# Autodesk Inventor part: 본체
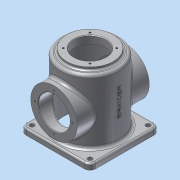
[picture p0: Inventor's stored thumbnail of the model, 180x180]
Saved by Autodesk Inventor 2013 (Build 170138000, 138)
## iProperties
Created: 2015-10
Part Number: 본체
Material: 알루미늄 6061
Document SubType Name: Modeling
Designer: ST4
Density: 2.71 g/cm^3
Mass: 989.141 g
Surface Area: 1040.66 cm^2
Volume: 364.997 cm^3
Author: ST4
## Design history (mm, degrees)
sketch "스케치1"
  geometry: L1 (-50, 60)-(50, 60); L2 (60, 50)-(60, -50); L3 (50, -60)-(-50, -60); L4 (-60, -50)-(-60, 50); A1 r 10 centre (-50, 50) between (-50, 60) and (-60, 50); A2 r 10 centre (50, 50) between (60, 50) and (50, 60); A3 r 10 centre (50, -50) between (50, -60) and (60, -50); A4 r 10 centre (-50, -50) between (-60, -50) and (-50, -60); 4 further points
  constraints: 8 end point, 8 point on circle, 8 tangent, 6 point on line, 4 centre point, 3 equal radius, 2 parallel, 1 horizontal, 1 perpendicular
  dimensions: "d0" = 120 distance of point (60, -60) point (-60, -60); "d2" = 120 distance of point (-60, -60) point (-60, 60); "d3" = 60 distance from line of point (0, 0) L3; "d4" = 60 distance from line of point (0, 0) L4; "d5" = 10 radius of A1
extrude "돌출1" new body sketch "스케치1" distance "d6" = 10; taper "d7" = 0 deg
sketch "스케치2"
  geometry: L1 (60, 10)-(60, 0) reference; L2 (60, 0)-(-60, 0) reference; L3 (-60, 0)-(-60, 10) reference; L4 (-60, 10)-(60, 10) reference; L5 (0, 0)-(0, 129.105); L6 (-28, 125)-(-40, 125); L7 (-40, 125)-(-40, 123); L8 (-43, 120)-(-45, 120); L9 (-50, 115)-(-50, 10); L10 (-27, 124)-(-27, 112); L11 (-27, 112)-(-42, 112); L12 (-45, 109)-(-45, 10); L13 (-28, 125)-(-27, 124); A1 r 5 centre (-45, 115) between (-45, 120) and (-50, 115); A2 r 3 centre (-43, 123) between (-43, 120) and (-40, 123); A3 r 3 centre (-42, 109) between (-42, 112) and (-45, 109); 2 further points
  constraints: 18 end point, 6 perpendicular, 6 point on circle, 6 point on line, 6 tangent, 3 centre point, 2 parallel
  dimensions: "d10" = 100 diameter of point (-50, 120) L5; "d11" = 80 diameter of L6.end L5; "d12" = 125 distance between parallel lines of L6 L2; "d14" = 110 distance between parallel lines of L8 L4; "d15" = 5 radius of A1; "d16" = 3 radius of A2; "d17" = 54 diameter of L10 L5; "d18" = 13 distance between parallel lines of L11 L6; "d19" = 90 diameter of L12 L5; "d20" = 1 distance of L6.start point (-27, 125); "d21" = 1 distance of L10.start point (-27, 125) (= d20); "d22" = 3 radius of A3
revolve "회전1" sketch "스케치2" stored, may be unused: angle "d23" = 90 deg
sketch "스케치3"
  geometry: C1 r 45 at (0, 0); 1 further point
  constraints: 1 centre point, 1 coincident
  dimensions: "d24" = 90 diameter of C1
extrude "돌출2" cut sketch "스케치3" distance "d26" = 10; taper "d27" = 0 deg
node "작업 평면1"
chamfer "모따기3" distance "d47" = 1; stored, may be unused: second distance "d48" = 2, angle "d49" = 45 deg
fillet "모깎기3" dims "d50" = 5
fillet "모깎기4" dims "d51" = 3
sketch "스케치6"
  geometry: C1 r 55 at (0, 0) reference; C2 r 4 at (50, -50); C3 r 4 at (50, 50); C4 r 4 at (-50, 50); C5 r 4 at (-50, -50); A1 r 7 centre (50, -50) between (50, -57) and (57, -50) reference
  constraints: 4 centre point, 1 coincident, 9 other
  dimensions: "d52" = 8 diameter of C2; "d56" = 360 deg dimension on C1.centre C2.centre (derived)
extrude "돌출5" cut sketch "스케치6" distance "d58" = 10; taper "d59" = 0 deg
sketch "스케치7" dims "d61" = 65
  geometry: L1 (0, 0)-(0, 28); L2 (0, 0)-(-28.284, 28.284); 3 further points
  constraints: 4 end point, 1 coincident, 1 point on line, 1 vertical, 1 vertical alignment, 6 other
  dimensions: "d60" = 45 deg angle of L1 L2
hole "구멍1" sketch "스케치7" at (-22.981, 22.981) diameter "d63" = 3.242; stored, may be unused: countersink angle "d67" = 90 deg, drill point angle "d69" = 118 deg; dims "d64" = 8, "d65" = 4, "d66" = 2, "d68" = 10
node "작업 평면3"
  node "작업 평면2"
sketch "스케치10"
  geometry: L1 (-5.17, -18.655)-(-5.17, 33.655); L2 (-5.17, 33.655)-(5.17, 33.655); L3 (5.17, 33.655)-(5.17, -18.655); L4 (5.17, -18.655)-(-5.17, -18.655); L5 (0, 33.655)-(0, -18.655); L6 (5.17, 7.5)-(-5.17, 7.5); L7 (-46, -62.5)-(46, -62.5) reference; 1 further point
  constraints: 4 end point, 4 midpoint, 2 other
  dimensions: "d98" = 0 distance from line of point (0, -62.5) L5; "d99" = 70 distance from line of L6.end L7
extrude "돌출6" join sketch "스케치10" stored distance "d100" = 10; taper "d101" = 0 deg
node "작업 평면4"
sketch "스케치11"
  geometry: L1 (50, 0)-(-50, 0) reference; C1 r 40 at (0, 60); 1 further point
  constraints: 1 centre point
  dimensions: "d103" = 80 diameter of C1; "d105" = 0 horizontal distance of point (0, 0) C1.centre; "d106" = 60 distance from line of L1 C1.centre
extrude "돌출7" join sketch "스케치11" stored distance "d107" = 10; taper "d108" = 0 deg
sketch "스케치12"
  geometry: C1 r 40 at (0, 0) reference; C2 r 27 at (0, 0); 1 further point
  constraints: 1 centre point, 1 coincident
  dimensions: "d109" = 54 diameter of C2
extrude "돌출8" cut sketch "스케치12" stored distance "d111" = 10; taper "d112" = 0 deg
chamfer "모따기4" distance "d113" = 1; stored, may be unused: second distance "d114" = 2, angle "d115" = 45 deg
fillet "모깎기5" dims "d116" = 5
fillet "모깎기6" dims "d117" = 3
chamfer "모따기5" distance "d118" = 1; stored, may be unused: second distance "d119" = 2, angle "d120" = 45 deg
sketch "스케치13"
  geometry: C1 r 40 at (0, 0) reference; 2 further points
  dimensions: "d121" = 0 vertical distance of point (32.5, 0) C1.centre; "d122" = 32.5 distance of C1.centre point (32.5, 0)
hole "구멍4" sketch "스케치13" at (32.5, 0) diameter "d123" = 3.242; stored, may be unused: countersink angle "d127" = 90 deg, drill point angle "d129" = 118 deg; dims "d124" = 8, "d125" = 4, "d126" = 2, "d128" = 10
node "솔리드1"
pattern_circular "원형 패턴1" dims angle "d71" = 360 deg
mirror "대칭2"
mirror "대칭3"
pattern_circular "원형 패턴4" dims angle "d131" = 360 deg
mirror "대칭4"
node "절단 모서리 투영1"
other parameters: "d28" = -62.5, "d97" = 0.5, "d102" = 62
